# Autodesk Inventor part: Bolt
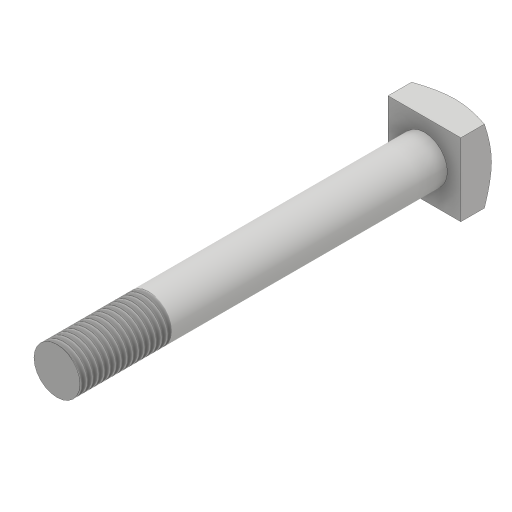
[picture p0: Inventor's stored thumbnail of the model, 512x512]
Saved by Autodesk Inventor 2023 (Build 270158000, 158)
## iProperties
Created: 2016-05
Part Number: Bolt
Material: Generic
Document SubType Name: Modeling
Designer: CADCIM
Density: 1 g/cm^3
Appearance: Default
Author: CADCIM
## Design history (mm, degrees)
sketch "Sketch1"
  geometry: L1 (9.5, 9.5)-(-9.5, 9.5); L2 (-9.5, 9.5)-(-9.5, -9.5); L3 (-9.5, -9.5)-(9.5, -9.5); L4 (9.5, -9.5)-(9.5, 9.5); L5 (0, 0)-(0, 14.108); L6 (0, 0)-(-17.802, 0)
  constraints: 12 end point, 2 horizontal, 2 parallel, 2 perpendicular, 1 vertical, 2 other
  dimensions: "d0" = 19 distance of L3.end L1.start
extrude "Extrusion1" new body sketch "Sketch1" distance "d1" = 8; taper "d2" = 0 deg
sketch "Sketch3"
  geometry: L1 (9.5, 9.5)-(-9.5, 9.5) reference; C1 r 9.5 at (0, 0); 1 further point
  constraints: 1 centre point, 1 coincident, 1 tangent
extrude "Extrusion3" sketch "Sketch3" distance "d6" = 96; taper "d7" = 65 deg
sketch "Sketch4"
  geometry: C1 r 6 at (0, 0); 1 further point
  constraints: 1 centre point, 1 coincident
  dimensions: "d10" = 12 diameter of C1
extrude "Extrusion4" join sketch "Sketch4" distance "d11" = 96; taper "d12" = 0 deg
thread "Thread2" dims "d13" = 24, "d14" = 0
body "Solid1"
